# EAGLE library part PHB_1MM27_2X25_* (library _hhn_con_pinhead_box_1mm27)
Pin Header Box-Type, 1.27mm/0.5"/50mil Pitch, 2x25 Circuits Note: see library description for an important note about THT-version
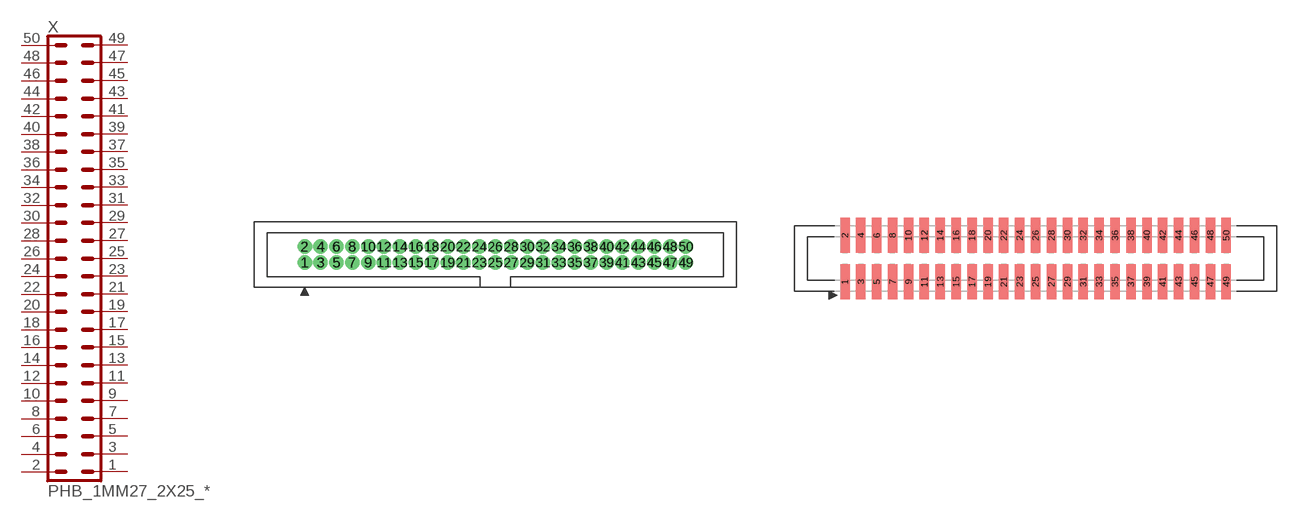
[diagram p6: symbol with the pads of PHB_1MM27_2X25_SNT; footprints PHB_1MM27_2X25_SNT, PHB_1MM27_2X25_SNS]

Designator prefix X

## PHB_1MM27_2X25_SNT  [PHB_1MM27_2X25_SNT]
1  1  pas
2  2  pas
3  3  pas
4  4  pas
5  5  pas
6  6  pas
7  7  pas
8  8  pas
9  9  pas
10  10  pas
11  11  pas
12  12  pas
13  13  pas
14  14  pas
15  15  pas
16  16  pas
17  17  pas
18  18  pas
19  19  pas
20  20  pas
21  21  pas
22  22  pas
23  23  pas
24  24  pas
25  25  pas
26  26  pas
27  27  pas
28  28  pas
29  29  pas
30  30  pas
31  31  pas
32  32  pas
33  33  pas
34  34  pas
35  35  pas
36  36  pas
37  37  pas
38  38  pas
39  39  pas
40  40  pas
41  41  pas
42  42  pas
43  43  pas
44  44  pas
45  45  pas
46  46  pas
47  47  pas
48  48  pas
49  49  pas
50  50  pas

## PHB_1MM27_2X25_SNS  [PHB_1MM27_2X25_SNS]
Pads as for PHB_1MM27_2X25_SNT

## Footprint PHB_1MM27_2X25_SNT (pad centres in mm)
Pin Header Box-Type, 1.27mm Pitch, 2x25 circuits, Straight, No Locking, THT Important Note: Diameter in this lbr is set to a specific value (NOT 'auto' = 0), this is ignored by actual eagle versions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
drill 0.65 pad 1 round: 1 -15.24,-0.635; 2 -15.24,0.635; 3 -13.97,-0.635; 4 -13.97,0.635; 5 -12.7,-0.635; 6 -12.7,0.635; 7 -11.43,-0.635; 8 -11.43,0.635; 9 -10.16,-0.635; 10 -10.16,0.635; 11 -8.89,-0.635; 12 -8.89,0.635; 13 -7.62,-0.635; 14 -7.62,0.635; 15 -6.35,-0.635; 16 -6.35,0.635; 17 -5.08,-0.635; 18 -5.08,0.635; 19 -3.81,-0.635; 20 -3.81,0.635; 21 -2.54,-0.635; 22 -2.54,0.635; 23 -1.27,-0.635; 24 -1.27,0.635; 25 0,-0.635; 26 0,0.635; 27 1.27,-0.635; 28 1.27,0.635; 29 2.54,-0.635; 30 2.54,0.635; 31 3.81,-0.635; 32 3.81,0.635; 33 5.08,-0.635; 34 5.08,0.635; 35 6.35,-0.635; 36 6.35,0.635; 37 7.62,-0.635; 38 7.62,0.635; 39 8.89,-0.635; 40 8.89,0.635; 41 10.16,-0.635; 42 10.16,0.635; 43 11.43,-0.635; 44 11.43,0.635; 45 12.7,-0.635; 46 12.7,0.635; 47 13.97,-0.635; 48 13.97,0.635; 49 15.24,-0.635; 50 15.24,0.635

## Footprint PHB_1MM27_2X25_SNS (pad centres in mm)
Pin Header Box-Type, 1.27mm Pitch, 2x25 circuits, Straight, No Locking, SMT
smd 0.76 x 2.8: 1 -15.24,-1.85; 2 -15.24,1.85; 3 -13.97,-1.85; 4 -13.97,1.85; 5 -12.7,-1.85; 6 -12.7,1.85; 7 -11.43,-1.85; 8 -11.43,1.85; 9 -10.16,-1.85; 10 -10.16,1.85; 11 -8.89,-1.85; 12 -8.89,1.85; 13 -7.62,-1.85; 14 -7.62,1.85; 15 -6.35,-1.85; 16 -6.35,1.85; 17 -5.08,-1.85; 18 -5.08,1.85; 19 -3.81,-1.85; 20 -3.81,1.85; 21 -2.54,-1.85; 22 -2.54,1.85; 23 -1.27,-1.85; 24 -1.27,1.85; 25 0,-1.85; 26 0,1.85; 27 1.27,-1.85; 28 1.27,1.85; 29 2.54,-1.85; 30 2.54,1.85; 31 3.81,-1.85; 32 3.81,1.85; 33 5.08,-1.85; 34 5.08,1.85; 35 6.35,-1.85; 36 6.35,1.85; 37 7.62,-1.85; 38 7.62,1.85; 39 8.89,-1.85; 40 8.89,1.85; 41 10.16,-1.85; 42 10.16,1.85; 43 11.43,-1.85; 44 11.43,1.85; 45 12.7,-1.85; 46 12.7,1.85; 47 13.97,-1.85; 48 13.97,1.85; 49 15.24,-1.85; 50 15.24,1.85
